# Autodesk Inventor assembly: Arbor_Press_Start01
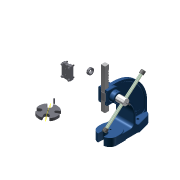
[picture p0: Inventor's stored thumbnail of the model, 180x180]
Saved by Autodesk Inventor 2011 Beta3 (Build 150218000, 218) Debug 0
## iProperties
Shininess: 64.0
Length Units: 11272
Angle Units: 11279
Time Units: 11290
Mass Units: 11286
Length Display Precision: 3
Angle Display Precision: 2
Compacted: True
Part Number: Arbor_Press_Start01
Document SubType Name: Assembly
Created: 2003-11
Designer: Autodesk, Inc
Manufacturer: Standard
Standards Organization: Custom
Mass: 8057.89 g
Surface Area: 2435.26 cm^2
Volume: 1030.81 cm^3
Density: 7.81702 g/cm^3
Density: 0.0
Volumn: 0.0
Area: 0.0
PropertySet Name: Model Information
Control State: 0
Master: False
Checked Out: False
Title: Arbor Press
Author: Autodesk, Inc
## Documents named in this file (15)
- C:\Users\Public\Documents\Autodesk\Inventor 2011\Tutorial Files\Arbor Press\Arbor_Press_Start01.iam
- C:\Users\Public\Documents\Autodesk\Inventor 2011\Tutorial Files\Arbor Press\Components\Arbor_Frame.ipt
- C:\Users\Public\Documents\Autodesk\Inventor 2011\Tutorial Files\Arbor Press\Components\COLLAR.ipt
- C:\Users\Public\Documents\Autodesk\Inventor 2011\Tutorial Files\Arbor Press\Components\PINION SHAFT.ipt
- C:\Users\Public\Documents\Autodesk\Inventor 2011\Tutorial Files\Arbor Press\Components\LEVER ARM.ipt
- C:\Users\Public\Documents\Autodesk\Inventor 2011\Tutorial Files\Arbor Press\Components\THUMB SCREW.ipt
- C:\Users\Public\Documents\Autodesk\Inventor 2011\Tutorial Files\Arbor Press\Components\GIB PLATE.ipt
- C:\Users\Public\Documents\Autodesk\Inventor 2011\Tutorial Files\Arbor Press\Components\GROOVE PIN.ipt
- C:\Users\Public\Documents\Autodesk\Inventor 2011\Tutorial Files\Arbor Press\Components\TABLE PLATE.ipt
- C:\Users\Public\Documents\Autodesk\Inventor 2011\Tutorial Files\Arbor Press\Components\RAM.ipt
- C:\Users\Public\Documents\Autodesk\Inventor 2011\Tutorial Files\Arbor Press\Components\HANDLE CAP.ipt
- C:\Users\Public\Documents\Autodesk\Inventor 2011\Tutorial Files\Arbor Press\Components\FACE PLATE.ipt
- C:\Users\Public\Documents\Autodesk\Inventor 2011\Tutorial Files\Arbor Press\Standard Parts\ANSI B18.3 - 1_4-20 UNC - 0.875(31).ipt
- C:\Users\Public\Documents\Autodesk\Inventor 2011\Tutorial Files\Arbor Press\Standard Parts\ISO 4766 - M5 x 5ISO.ipt
- C:\Users\Public\Documents\Autodesk\Inventor 2011\Tutorial Files\Arbor Press\Standard Parts\BS 4168 - M5 x 16(2).ipt
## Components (21 placed, 14 different names)
1. Arbor_Frame:1 — Mate:1, Insert:7, Angle SHAFT TURN, Mate:14, Flush:11, Flush:12, Mate:15, Flush:13, Mate:25, Flush:21, Mate:26, Flush:22, Flush:23, Flush:24, Mate:25, Mate:27, Flush:25
2. PINION SHAFT:1 — Mate:3, Insert:7, Rotation/Translation:1, Angle SHAFT TURN, Mate:12, Insert:12, Mate:17
3. RAM:1 — Mate:1, Rotation/Translation:1, Flush:11
4. THUMB SCREW:1 — Insert:12, Mate:17
5. GROOVE PIN:1
6. TABLE PLATE:1
7. ISO 4766 M5 x 5:1 — Mate:28, Tangent:1
8. COLLAR:1 — Mate:28, Tangent:1
9. GIB PLATE:1 — Flush:2, Mate:25, Mate:27, Flush:25
10. FACE PLATE:1 — Flush:2, Mate:14, Flush:12, Mate:23, Flush:19, Mate:24, Flush:20, Flush:23, Flush:24
11. BS 4168 : Part 2 Hexagon socket screws and wrench keys, metric series- Specification for hexagon set screws with flat point - Metric M5 x 16:3 — Mate:26, Flush:22
12. BS 4168 : Part 2 Hexagon socket screws and wrench keys, metric series- Specification for hexagon set screws with flat point - Metric M5 x 16:4 — Mate:25, Flush:21
13. LEVER ARM:1 — Mate:3, Mate:12
14. HANDLE CAP:1
15. HANDLE CAP:2
16. BS 4168 : Part 2 Hexagon socket screws and wrench keys, metric series- Specification for hexagon set screws with flat point - Metric M5 x 16:1 — Mate:23, Flush:19
17. BS 4168 : Part 2 Hexagon socket screws and wrench keys, metric series- Specification for hexagon set screws with flat point - Metric M5 x 16:2 — Mate:24, Flush:20
18. Hexagon Socket Head Cap Screw - Inch 1/4 - 20 UNC - 7/8:1
19. Hexagon Socket Head Cap Screw - Inch 1/4 - 20 UNC - 7/8:2
20. Hexagon Socket Head Cap Screw - Inch 1/4 - 20 UNC - 7/8:3
21. Hexagon Socket Head Cap Screw - Inch 1/4 - 20 UNC - 7/8:4
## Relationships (29: Mate 13, Flush 11, Insert 2, RelateRotateTranslate 1, Angle 1, Tangent 1)
- Mate:1: Arbor_Frame:1 ↔ RAM:1
- Mate:3: PINION SHAFT:1 ↔ LEVER ARM:1
- Insert:7: Arbor_Frame:1 ↔ PINION SHAFT:1
- Flush:2: GIB PLATE:1 ↔ FACE PLATE:1
- Rotation/Translation:1 [RelateRotateTranslate]: PINION SHAFT:1 ↔ RAM:1
- Angle SHAFT TURN: Arbor_Frame:1 ↔ PINION SHAFT:1
- Mate:12: PINION SHAFT:1 ↔ LEVER ARM:1
- Mate:14: Arbor_Frame:1 ↔ FACE PLATE:1
- Flush:11: Arbor_Frame:1 ↔ RAM:1
- Flush:12: Arbor_Frame:1 ↔ FACE PLATE:1
- Mate:15: Arbor_Frame:1
- Flush:13: Arbor_Frame:1
- Insert:12: PINION SHAFT:1 ↔ THUMB SCREW:1
- Mate:17: PINION SHAFT:1 ↔ THUMB SCREW:1
- Mate:23: FACE PLATE:1 ↔ BS 4168 : Part 2 Hexagon socket screws and wrench keys, metric series- Specification for hexagon set screws with flat point - Metric M5 x 16:1
- Flush:19: FACE PLATE:1 ↔ BS 4168 : Part 2 Hexagon socket screws and wrench keys, metric series- Specification for hexagon set screws with flat point - Metric M5 x 16:1
- Mate:24: FACE PLATE:1 ↔ BS 4168 : Part 2 Hexagon socket screws and wrench keys, metric series- Specification for hexagon set screws with flat point - Metric M5 x 16:2
- Flush:20: FACE PLATE:1 ↔ BS 4168 : Part 2 Hexagon socket screws and wrench keys, metric series- Specification for hexagon set screws with flat point - Metric M5 x 16:2
- Mate:25: Arbor_Frame:1 ↔ BS 4168 : Part 2 Hexagon socket screws and wrench keys, metric series- Specification for hexagon set screws with flat point - Metric M5 x 16:4
- Flush:21: Arbor_Frame:1 ↔ BS 4168 : Part 2 Hexagon socket screws and wrench keys, metric series- Specification for hexagon set screws with flat point - Metric M5 x 16:4
- Mate:26: Arbor_Frame:1 ↔ BS 4168 : Part 2 Hexagon socket screws and wrench keys, metric series- Specification for hexagon set screws with flat point - Metric M5 x 16:3
- Flush:22: Arbor_Frame:1 ↔ BS 4168 : Part 2 Hexagon socket screws and wrench keys, metric series- Specification for hexagon set screws with flat point - Metric M5 x 16:3
- Flush:23: Arbor_Frame:1 ↔ FACE PLATE:1
- Flush:24: Arbor_Frame:1 ↔ FACE PLATE:1
- Mate:25: Arbor_Frame:1 ↔ GIB PLATE:1
- Mate:27: Arbor_Frame:1 ↔ GIB PLATE:1
- Flush:25: Arbor_Frame:1 ↔ GIB PLATE:1
- Mate:28: ISO 4766 M5 x 5:1 ↔ COLLAR:1
- Tangent:1: ISO 4766 M5 x 5:1 ↔ COLLAR:1
